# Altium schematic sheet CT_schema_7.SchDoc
size 287 x 160 mm
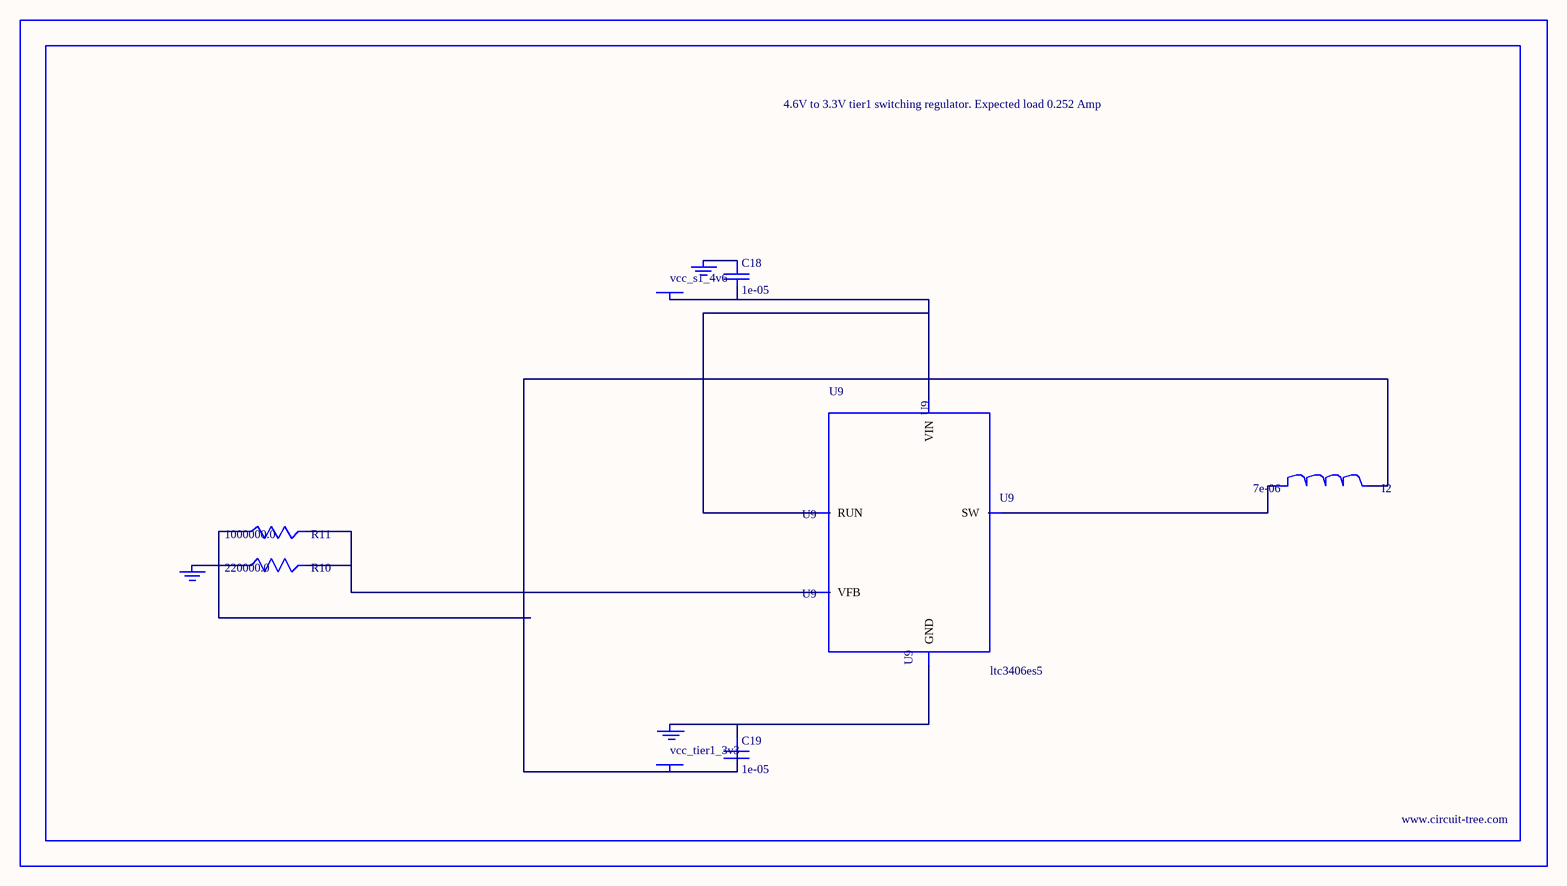
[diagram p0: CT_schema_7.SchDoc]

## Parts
BORDER6  (no value)
C18  1e-05  [C0805]
C19  1e-05  [C0805]
GND_INSTANCE_6_0  (no value)
GND_INSTANCE_6_1  (no value)
GND_INSTANCE_6_2  (no value)
I2  7e-06  [DR1040]
POWER_INSTANCE_6_0  vcc_tier1_3v3
POWER_INSTANCE_6_1  vcc_s1_4v6
R10  220000.0  [R0603]
R11  1000000.0  [R0603]
U9  ltc3406es5  [TSOT-23-5]

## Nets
NetC18_1: C18.1 GND_INSTANCE_6_1.0(GND)
NetC18_2: C18.2 POWER_INSTANCE_6_1.0(PWR) U9.1(RUN) U9.4(VIN)
NetC19_1: C19.1 GND_INSTANCE_6_0.0(GND) U9.2(GND)
NetC19_2: C19.2 I2.2 POWER_INSTANCE_6_0.0(PWR) R11.1
NetGND_INSTANCE_6_2_0: GND_INSTANCE_6_2.0(GND) R10.1
NetI2_1: I2.1 U9.3(SW)
NetR10_2: R10.2 R11.2 U9.5(VFB)

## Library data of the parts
BORDER6 = BORDER_PAGE6
C18 C19 = C0805C106K8RACTU
GND_INSTANCE_6_0-GND_INSTANCE_6_2 = GND
I2 = DR1040-7R0-R
POWER_INSTANCE_6_0 POWER_INSTANCE_6_1 = PWR
R10 = RC0603JR-07220KL
R11 = RC0603JR-071ML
